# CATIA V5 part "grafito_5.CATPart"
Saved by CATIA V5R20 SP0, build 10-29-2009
Part number: grafito_5
Revision: ANY
Definition: UNKNOWN
Nomenclature: grafito
Source: Unknown
Bounding box of the stored display mesh (mm): x -2.498 to 2.497, y 2.142 to 22.11, z -2.5 to 2.5
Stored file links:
  C:\Users\Utente\Desktop\IO LAVORO\3D X SITO CF\CUMSA\3D files SD\SD 4528\grafito_5.CATPart
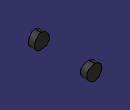
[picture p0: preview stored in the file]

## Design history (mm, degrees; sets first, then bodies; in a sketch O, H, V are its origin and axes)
Body1 "Saliente-Extruir1" (main body)
  Solid1: solid without history
Body2 "Saliente-Extruir1"
  Solid2: solid without history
